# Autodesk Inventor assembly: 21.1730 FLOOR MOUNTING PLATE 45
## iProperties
Created: 2007-04
Part Number: 21.1730 FLOOR MOUNTING PLATE 45
Document SubType Name: Assembly
Designer: Andy Moles
Author: Andy Moles
